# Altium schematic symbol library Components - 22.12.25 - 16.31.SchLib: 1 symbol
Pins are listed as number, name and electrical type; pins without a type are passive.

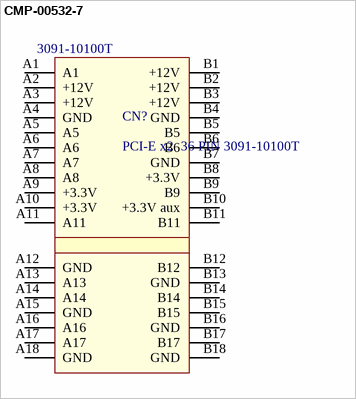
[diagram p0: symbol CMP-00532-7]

## CMP-00532-7
designator CN?, comment PCI-E x2  36 PIN 3091-10100T  Part Number: 3091-10100T
PCI-E x2 1mm Right-Angle 98P -40℃~+85℃ Push-Pull,P=1mm Card Edge Connectors ROHS; Manufacturer: UMAX
footprint PCIE-036-02-X-D-RA UMAX 3091-10100T
pins: A1, A2 +12V, A3 +12V, A4 GND, A5, A6, A7, A8, A9 +3.3V, A10 +3.3V, A11, A12 GND, A13, A14, A15 GND, A16, A17, A18 GND, B1 +12V, B2 +12V, B3 +12V, B4 GND, B5, B6, B7 GND, B8 +3.3V, B9, B10 +3.3V aux, B11, B12, B13 GND, B14, B15, B16 GND, B17, B18 GND
2 alternate drawings of the same symbol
